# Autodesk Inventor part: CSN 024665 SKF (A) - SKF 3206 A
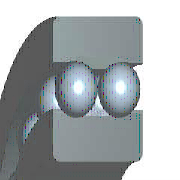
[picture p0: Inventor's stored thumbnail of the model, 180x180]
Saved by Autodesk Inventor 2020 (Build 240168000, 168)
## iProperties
IsCustomPart: 0
Created: 2019-01
Part Number: CSN 024665 SKF (A) - SKF 3206 A
Material: Ocel, měkká
Description: Kuličková ložiska dvouřadá s kosoúhlým dotykem SKF
Document SubType Name: Modeling
Standard: CSN 024665 SKF
Designer: doma
Standards Organization: CSN
Language: cs-CZ
Size Designation: SKF 3206 A
Categories: <MemberInstance><Categories><Category DisplayName="Součásti hřídele" InternalName="7f7aeb1f-a693-4053-b835-cee3144e0d98" Mnemonic="SHFT"><Category DisplayName="
Density: 7.85 g/cm^3
Appearance: Pololeštěná
Mass: 266.285 g
Surface Area: 202.804 cm^2
Volume: 33.9216 cm^3
Author: doma
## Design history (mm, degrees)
node "WorkPlane2"
node "WorkPlane4"
workplane "Work Plane3"
node "WorkPlane6"
node "WorkPoint1"
node "WorkPlane3"
node "WorkPlane5"
node "WorkPoint2"
node "WorkAxis1"
sketch "Náčrt4"
  geometry: C1 r 31 at (0, 0) reference
hole "Otvor1" sketch "Náčrt4" diameter "d6" = 30 (= Diam); stored, may be unused: countersink angle "d10" = 60 deg, drill point angle "d12" = 118 deg; dims "d7" = 6, "d8" = 4, "d9" = 2, "d11" = 8
pattern_circular "PolarArray1" dims angle "d25" = 360 deg
pattern_circular "PolarArray2" dims angle "d31" = 360 deg
body "Solid1"
node "Náčrt1"
extrude "Vysunutí1" new body distance "d3" = 23.8 (= B); taper "d4" = 0 deg
node "Náčrt3"
revolve "Rotace1" stored, may be unused: angle "d19" = 360 deg
revolve "Rotace2" stored, may be unused: angle "d22" = 360 deg
revolve "Rotace3" stored, may be unused: angle "d28" = 360 deg
fillet "Zaoblení1" dims "d32" = 1 (= r)
node "Náčrt2" dims "d2" = 62 (= DD)
sketch "Náčrt5"
  geometry: L1 (27.48, 23.8)-(27.48, 19.32); L2 (20.312, 23.8)-(27.48, 23.8); L3 (20.312, 22.904)-(20.312, 23.8); L4 (18.52, 4.48)-(18.52, 19.32); L5 (20.312, 0)-(20.312, 0.896); L6 (27.48, 0)-(20.312, 0); L7 (27.48, 4.48)-(27.48, 0); L8 (25.688, 15.736)-(25.688, 8.064); L9 (-31, 23.8)-(31, 23.8) reference; L10 (-31, 0)-(31, 0) reference; L11 (0, 29.338)-(0, -15.338); L12 (0, -24.274)-(0, 38.274) reference; A1 r 4.48 centre (23, 19.32) between (25.688, 15.736) and (27.48, 19.32); A2 r 4.48 centre (23, 19.32) between (20.312, 22.904) and (18.52, 19.32); A3 r 4.48 centre (23, 4.48) between (18.52, 4.48) and (20.312, 0.896); A4 r 4.48 centre (23, 4.48) between (27.48, 4.48) and (25.688, 8.064)
  constraints: 18 end point, 8 point on circle, 6 vertical, 5 collinear, 4 centre point, 4 tangent, 2 concentric, 2 equal radius, 2 horizontal
  dimensions: "d14" = 4.48 horizontal distance of A2.centre L1.start (= 0.5 x msp_dd0); "d16" = 4.48 horizontal distance of A4.centre L6.start (= 0.5 x msp_dd0); "d18" = 4.48 radius of A1 (= 0.5 x msp_dd0); "d33" = 46 diameter of A2.centre L11 (= msp_mdtds); "d34" = 40.624 diameter of L3.start L11 (= msp_dd2); "d35" = 51.376 diameter of L8 L11 (= msp_vd2)
sketch "Náčrt6"
  geometry: L1 (23, 8.96)-(23, 0); L2 (-31, 0)-(31, 0) reference; L3 (-27.48, 23.8)-(27.48, 23.8) reference; L4 (23, 8.96)-(23, 0); A1 r 4.48 centre (23, 4.48) between (23, 8.96) and (23, 0); A2 r 4.48 centre (23, 4.48) between (18.52, 4.48) and (20.312, 0.896) reference
  constraints: 4 end point, 2 point on circle, 1 centre point, 1 concentric, 1 midpoint, 1 vertical
  dimensions: "d21" = 4.48 radius of A1 (= 0.5 x msp_dd0)
sketch "Náčrt7"
  geometry: L1 (23, 23.8)-(23, 14.84); L2 (-27.48, 23.8)-(27.48, 23.8) reference; L3 (15, 0)-(-15, 0) reference; L4 (23, 23.8)-(23, 14.84); A1 r 4.48 centre (23, 19.32) between (23, 23.8) and (23, 14.84); A2 r 4.48 centre (23, 19.32) between (20.312, 22.904) and (18.52, 19.32) reference
  constraints: 4 end point, 2 point on circle, 1 centre point, 1 concentric, 1 midpoint, 1 vertical
  dimensions: "d27" = 4.48 radius of A1 (= 0.5 x msp_dd0)
other parameters: "Diam" = 30 [user parameter; used in 3 equation terms], "DD" = 62 [user parameter; used in 3 equation terms], "B" = 23.8 [user parameter; used in 2 equation terms], "r" = 1 [user parameter; used in 1 equation term], "msp_mdtds" = 46 (= 0.5 x Diam + 0.5 x DD) [user parameter; used in 4 equation terms], "msp_dd0" = 8.96 (= -0.28 x Diam + 0.28 x DD) [user parameter; used in 8 equation terms], "msp_dd2" = 40.624 (= msp_mdtds - 0.6 x msp_dd0) [user parameter; used in 1 equation term], "msp_ang" = 0 [user parameter], "msp_vd2" = 51.376 (= msp_mdtds + 0.6 x msp_dd0) [user parameter; used in 1 equation term], "d0" = -23.8 (computed from B), "d5" = 0, "d13" = 2.8 (derived), "d15" = 2.8 (derived), "d17" = 2.8 (derived), "d20" = 2.8 (derived), "d26" = 2.8 (derived), "d38" = 0, "d39" = 0, "d40" = 0, "d41" = 0, "d42" = 0
